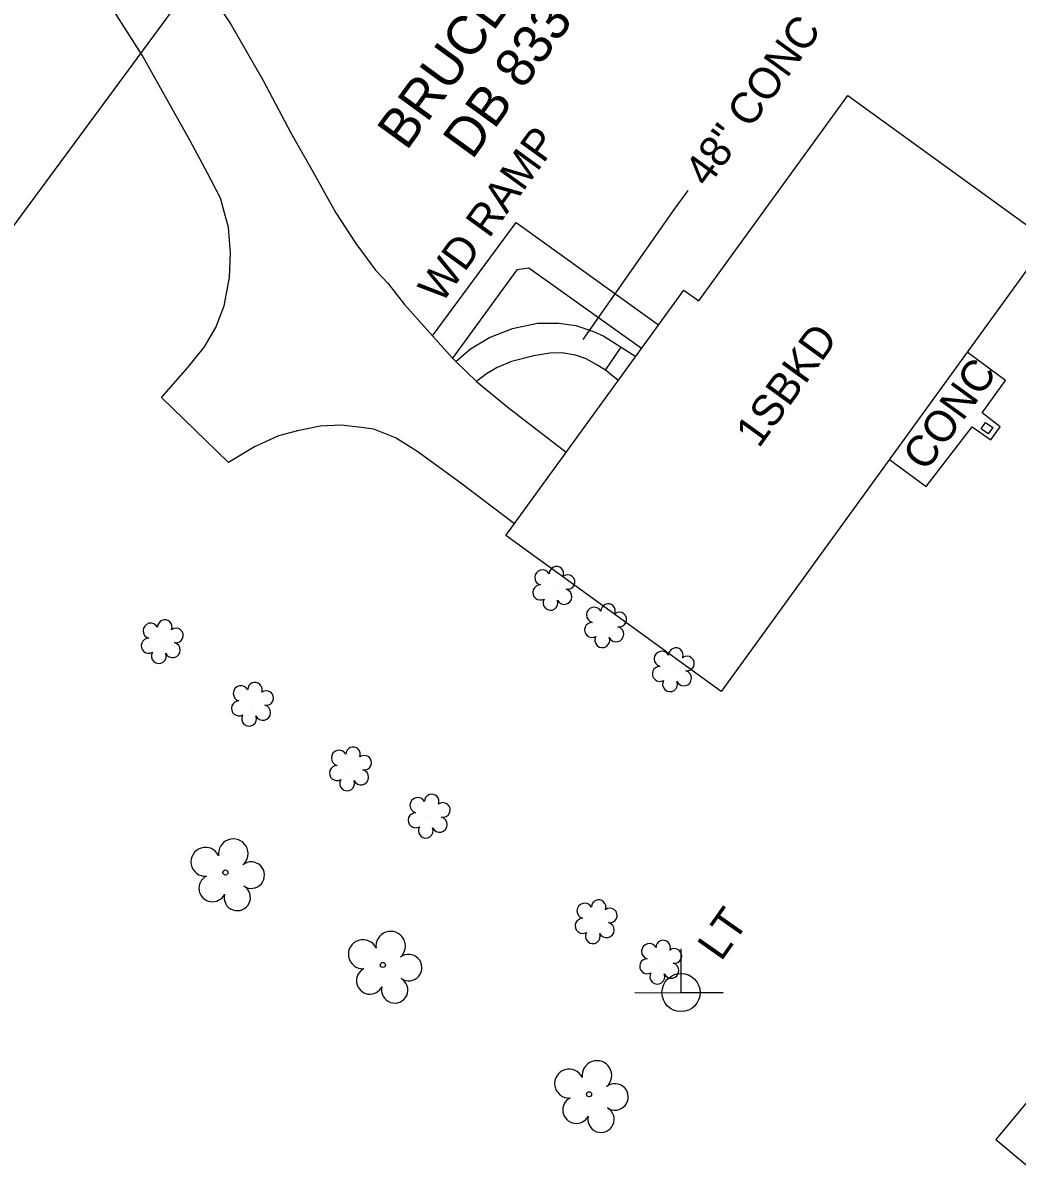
# Model space of a CAD drawing. Extents: x 1182322 to 1186765, y 572295 to 575411.
# Drawn here: x 1183934.6 to 1184062.3, y 573028.6 to 573175 of the extents above; entities that cross this region are included whole.
import ezdxf

# ---------------------------------------------------------------- set-up
doc = ezdxf.new("R2010")
doc.units = 0
for name, color, linetype in [('Exist Building', 7, 'Continuous'), ('Exist Building Text', 7, 'Continuous'), ('Exist Other Culture Area Outline', 7, 'Continuous'), ('Exist Other Culture Area Outline Leader', 7, 'Continuous'), ('Exist Other Culture Area Outline Text', 7, 'Continuous'), ('Exist Property Deed Book Text', 7, 'Continuous'), ('Exist Property Owner Text', 7, 'Continuous'), ('Exist Right of Way Line', 7, 'Continuous'), ('Exist Roads EOP Other', 7, 'Continuous'), ('Exist Structure Minor Drop Inlet', 7, 'Continuous'), ('Exist Utilities Power Joint Use Telephone CELL', 7, 'Continuous'), ('Exist Utilities Power Joint Use Telephone Text', 7, 'Continuous'), ('Exist Vegetation Shrub CELL', 7, 'Continuous'), ('Exist Vegetation Tree CELL', 7, 'Continuous')]:
    doc.layers.add(name, color=color, linetype=linetype)

msp = doc.modelspace()

# ---------------------------------------------------------------- linework, layer by layer
at = {"layer": 'Exist Building'}
for points in [[(1184066.27, 573147.04), (1184024.29, 573089.15), (1183996.64, 573109.19), (1184019.49, 573140.7), (1184021.42, 573139.3), (1184040.55, 573165.69)], [(1184077.75, 573016.46), (1184102.27, 573045.83), (1184084.07, 573061.03), (1184059.55, 573031.66)]]:
    msp.add_lwpolyline(points, close=True, dxfattribs=at)
at = {"layer": 'Exist Other Culture Area Outline'}
for points in [[(1183987.22, 573134.83), (1183997.94, 573149.35), (1184016.25, 573136.24)], [(1184014.03, 573133.18), (1183999.58, 573143.49), (1183998.02, 573143.31), (1183989.76, 573131.93)], [(1183990.21, 573131.54), (1183992.08, 573133.15), (1183994.52, 573134.59), (1183997.49, 573135.75), (1184000.71, 573136.46), (1184003.44, 573136.46), (1184005.62, 573136.15), (1184007.9, 573135.37), (1184009.2, 573134.77), (1184011.44, 573133.35)], [(1184009.42, 573130.41), (1184008.21, 573131.14), (1184006.96, 573131.85), (1184005.56, 573132.32), (1184003.81, 573132.62), (1184002.26, 573132.61), (1184000.23, 573132.24), (1183997.34, 573131.52), (1183995.51, 573130.74), (1183994.14, 573129.96), (1183992.85, 573128.96)], [(1184011.06, 573129.08), (1184009.42, 573130.41), (1184011.44, 573133.35), (1184013.3, 573132.17)], [(1184045.9, 573118.95), (1184050.59, 573115.48), (1184056.51, 573123.15), (1184058.91, 573121.45), (1184060.13, 573123.14), (1184057.79, 573124.93), (1184060.8, 573129.09), (1184055.88, 573132.71)]]:
    msp.add_lwpolyline(points, dxfattribs=at)
at = {"layer": 'Exist Other Culture Area Outline Leader'}
msp.add_lwpolyline([(1184006.56, 573134.34), (1184018.28, 573151.06), (1184020.04, 573153.49)], dxfattribs=at)
at = {"layer": 'Exist Right of Way Line'}
msp.add_line((1183893.87, 573095.33), (1184001.04, 573240.75), dxfattribs=at)
at = {"layer": 'Exist Roads EOP Other'}
for points in [[(1183952.04, 573187.75), (1183955.02, 573183.93), (1183958.49, 573179.12), (1183961.35, 573174.75), (1183965.45, 573167.59), (1183968.99, 573160.89), (1183971.66, 573156.22), (1183974.77, 573150.6), (1183977.34, 573146.68), (1183979.87, 573143.25), (1183981.46, 573141.57), (1183983.62, 573138.83), (1183987.22, 573134.83), (1183989.76, 573131.93), (1183990.21, 573131.54), (1183992.85, 573128.96), (1183996.92, 573125.62), (1184004.39, 573119.87)], [(1183997.72, 573110.67), (1183990.69, 573116.03), (1183985.17, 573119.99), (1183982.43, 573121.74), (1183979.68, 573122.82), (1183978.05, 573123.07), (1183975.48, 573123.35), (1183972.77, 573123.24), (1183969.85, 573122.62), (1183967.41, 573121.97), (1183964.35, 573120.55), (1183961.01, 573118.56), (1183952.39, 573126.91), (1183955.79, 573130.74), (1183957.9, 573133.42), (1183959.38, 573135.89), (1183960.44, 573138.66), (1183961.14, 573142.29), (1183961.28, 573145.49), (1183961.01, 573148.72), (1183959.96, 573152.49), (1183958.28, 573155.8), (1183956.06, 573159.84), (1183949.91, 573170.86), (1183943.42, 573181.06)]]:
    msp.add_lwpolyline(points, dxfattribs=at)
at = {"layer": 'Exist Structure Minor Drop Inlet'}
msp.add_lwpolyline([(1184057.68, 573122.88), (1184058.24, 573123.7), (1184059.16, 573123.07), (1184058.59, 573122.25)], close=True, dxfattribs=at)
at = {"layer": 'Exist Utilities Power Joint Use Telephone CELL'}
msp.add_line((1184019.13, 573050.51), (1184019.13, 573050.51), dxfattribs=at)
msp.add_lwpolyline([(1184013.19, 573050.51), (1184024.53, 573050.47), (1184019.13, 573050.49), (1184019.13, 573056.13)], dxfattribs=at)
msp.add_circle((1184019.13, 573050.51), 2.45, dxfattribs=at)
at = {"layer": 'Exist Vegetation Shrub CELL'}
for p, q in [((1184002.85, 573102.41), (1184002.85, 573102.41)), ((1184009.49, 573097.61), (1184009.49, 573097.61)), ((1183952.54, 573095.57), (1183952.54, 573095.57)), ((1184018.19, 573091.96), (1184018.19, 573091.96)), ((1183964.13, 573087.53), (1183964.13, 573087.53)), ((1183976.72, 573079.24), (1183976.72, 573079.24)), ((1183986.82, 573073.17), (1183986.82, 573073.17)), ((1184008.27, 573059.62), (1184008.27, 573059.62)), ((1184016.57, 573054.42), (1184016.57, 573054.42))]:
    msp.add_line(p, q, dxfattribs=at)
for centre, radius, start, end in [((1184001.33, 573103.79), 0.99, 28.9927, 254.6254), ((1184003.12, 573104.28), 0.929, 338.6103, 180.2398), ((1184001.06, 573101.87), 0.968, 90.0444, 299.5753), ((1184004.56, 573103.2), 0.937, 259.145, 127.6137), ((1184004.13, 573101.32), 0.984, 205.4333, 75.5406), ((1184002.36, 573100.54), 0.955, 149.2636, 22.107), ((1184007.97, 573098.99), 0.99, 28.9927, 254.6254), ((1184009.76, 573099.48), 0.929, 338.6103, 180.2398), ((1183952.82, 573097.43), 0.929, 338.6103, 180.2398), ((1184011.2, 573098.4), 0.937, 259.145, 127.6137), ((1183951.02, 573096.95), 0.99, 28.9927, 254.6254), ((1183954.26, 573096.35), 0.937, 259.145, 127.6137), ((1184007.71, 573097.07), 0.968, 90.0444, 299.5753), ((1184010.78, 573096.52), 0.984, 205.4333, 75.5406), ((1183950.76, 573095.03), 0.968, 90.0444, 299.5753), ((1183953.83, 573094.48), 0.984, 205.4333, 75.5406), ((1184009.01, 573095.74), 0.955, 149.2636, 22.107), ((1183952.06, 573093.7), 0.955, 149.2636, 22.107), ((1184016.67, 573093.34), 0.99, 28.9927, 254.6254), ((1184018.46, 573093.83), 0.929, 338.6103, 180.2398), ((1184019.9, 573092.75), 0.937, 259.145, 127.6137), ((1184016.41, 573091.42), 0.968, 90.0444, 299.5753), ((1184019.48, 573090.87), 0.984, 205.4333, 75.5406), ((1183962.61, 573088.91), 0.99, 28.9927, 254.6254), ((1183964.4, 573089.4), 0.929, 338.6103, 180.2398), ((1184017.71, 573090.09), 0.955, 149.2636, 22.107), ((1183965.84, 573088.32), 0.937, 259.145, 127.6137), ((1183962.35, 573086.99), 0.968, 90.0444, 299.5753), ((1183965.42, 573086.44), 0.984, 205.4333, 75.5406), ((1183963.64, 573085.66), 0.955, 149.2636, 22.107), ((1183975.2, 573080.62), 0.99, 28.9927, 254.6254), ((1183977, 573081.1), 0.929, 338.6103, 180.2398), ((1183978.43, 573080.02), 0.937, 259.145, 127.6137), ((1183974.94, 573078.69), 0.968, 90.0444, 299.5753), ((1183976.24, 573077.36), 0.955, 149.2636, 22.107), ((1183978.01, 573078.15), 0.984, 205.4333, 75.5406), ((1183985.3, 573074.55), 0.99, 28.9927, 254.6254), ((1183987.1, 573075.04), 0.929, 338.6103, 180.2398), ((1183988.54, 573073.95), 0.937, 259.145, 127.6137), ((1183985.04, 573072.63), 0.968, 90.0444, 299.5753), ((1183988.11, 573072.08), 0.984, 205.4333, 75.5406), ((1183986.34, 573071.3), 0.955, 149.2636, 22.107), ((1184006.75, 573061), 0.99, 28.9927, 254.6254), ((1184008.54, 573061.48), 0.929, 338.6103, 180.2398), ((1184009.98, 573060.4), 0.937, 259.145, 127.6137), ((1184006.49, 573059.07), 0.968, 90.0444, 299.5753), ((1184009.56, 573058.53), 0.984, 205.4333, 75.5406), ((1184007.79, 573057.74), 0.955, 149.2636, 22.107), ((1184015.05, 573055.8), 0.99, 28.9927, 254.6254), ((1184016.84, 573056.29), 0.929, 338.6103, 180.2398), ((1184018.28, 573055.21), 0.937, 259.145, 127.6137), ((1184014.78, 573053.88), 0.968, 90.0444, 299.5753), ((1184016.08, 573052.55), 0.955, 149.2636, 22.107), ((1184017.85, 573053.33), 0.984, 205.4333, 75.5406)]:
    msp.add_arc(centre, radius, start, end, dxfattribs=at)
at = {"layer": 'Exist Vegetation Tree CELL'}
for p, q in [((1183960.6, 573065.92), (1183960.6, 573065.92)), ((1183980.82, 573054.05), (1183980.82, 573054.05)), ((1184007.31, 573037.45), (1184007.31, 573037.45))]:
    msp.add_line(p, q, dxfattribs=at)
for centre in [(1183960.6, 573065.92), (1183980.82, 573054.05), (1184007.31, 573037.45)]:
    msp.add_circle(centre, 0.326, dxfattribs=at)
for centre, radius, start, end in [((1183958.04, 573067.29), 1.86, 24.3187, 273.867), ((1183961.61, 573068.33), 1.9, 311.2547, 188.3536), ((1183963.92, 573065.58), 1.7, 235.4358, 128.7136), ((1183958.94, 573063.9), 1.73, 116.8172, 333.4993), ((1183962.13, 573062.71), 1.69, 165.7207, 60.3847), ((1183981.83, 573056.46), 1.9, 311.2547, 188.3536), ((1183978.26, 573055.42), 1.86, 24.3187, 273.867), ((1183984.15, 573053.71), 1.7, 235.4358, 128.7136), ((1183979.17, 573052.03), 1.73, 116.8172, 333.4993), ((1183982.35, 573050.84), 1.69, 165.7207, 60.3847), ((1184008.32, 573039.86), 1.9, 311.2547, 188.3536), ((1184004.75, 573038.82), 1.86, 24.3187, 273.867), ((1184010.64, 573037.11), 1.7, 235.4358, 128.7136), ((1184005.66, 573035.43), 1.73, 116.8172, 333.4993), ((1184008.84, 573034.24), 1.69, 165.7207, 60.3847)]:
    msp.add_arc(centre, radius, start, end, dxfattribs=at)

# ---------------------------------------------------------------- texts
at = {"layer": 'Exist Building Text'}
msp.add_text('1SBKD', height=4, rotation=54.0563, dxfattribs=at).set_placement((1184029.11, 573120.28))
at = {"layer": 'Exist Other Culture Area Outline Text'}
for s, rotation, p in [('48" CONC', 54.0596, (1184022.53, 573153.74)), ('WD RAMP', 54.0596, (1183988.35, 573138.81)), ('CONC', 54.0563, (1184050.57, 573117.26))]:
    msp.add_text(s, height=4, rotation=rotation, dxfattribs=at).set_placement(p)
at = {"layer": 'Exist Property Deed Book Text'}
msp.add_text('DB 833 PG 13', height=5, rotation=54.0376, dxfattribs=at).set_placement((1183992.28, 573157.3))
at = {"layer": 'Exist Property Owner Text'}
msp.add_text('BRUCE KENNEDY', height=5, rotation=54.0376, dxfattribs=at).set_placement((1183983.86, 573158.47))
at = {"layer": 'Exist Utilities Power Joint Use Telephone Text'}
msp.add_text('LT', height=4, rotation=54.8611, dxfattribs=at).set_placement((1184024.27, 573054.4))

doc.saveas('drawing.dxf')
